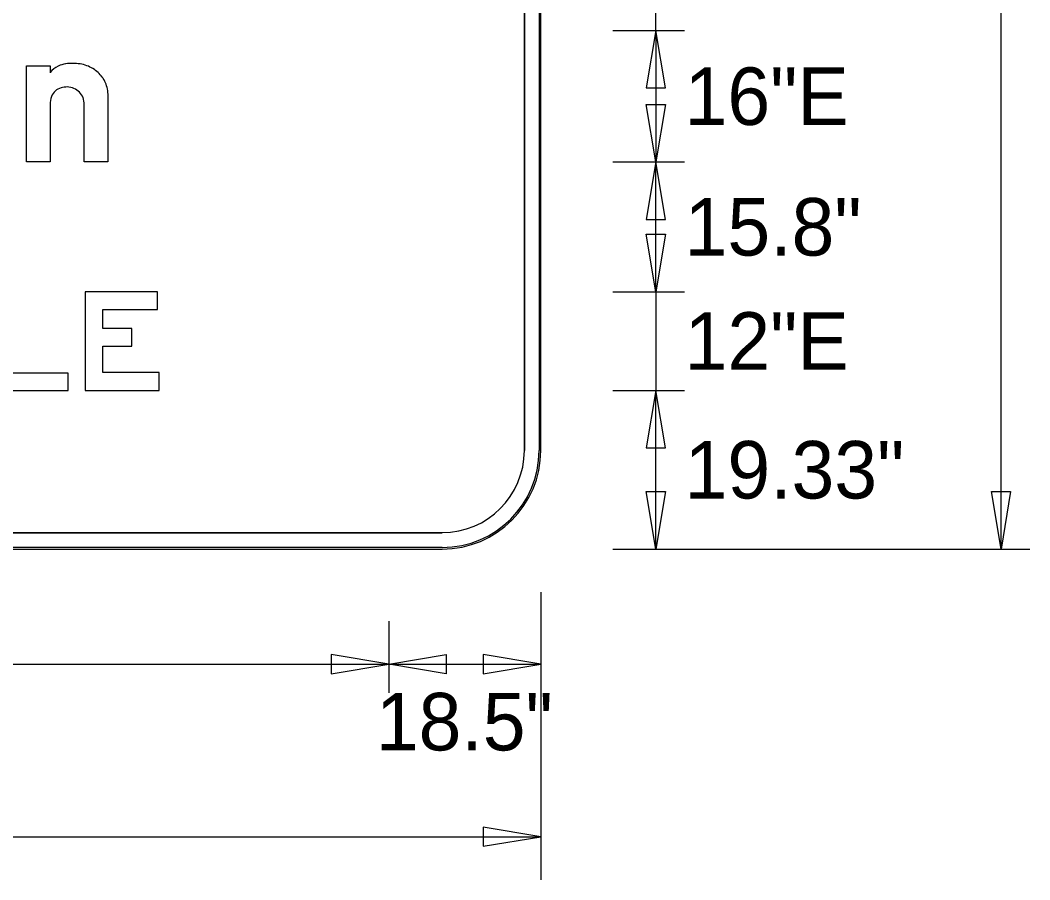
# Model space of a CAD drawing. Extents: x 2149934 to 2150188, y 145113 to 145238.
# Drawn here: x 2150041.74 to 2150051.98, y 145141.03 to 145149.75 of the extents above; entities that cross this region are included whole.
import ezdxf

# ---------------------------------------------------------------- set-up
doc = ezdxf.new("R2010")
doc.units = 0
for name, color, linetype in [('GSBWFILL', 7, 'Continuous'), ('GSCOLORFILL', 7, 'Continuous'), ('GSDIMS', 7, 'Continuous'), ('GSOUTLINE', 7, 'Continuous')]:
    doc.layers.add(name, color=color, linetype=linetype)

msp = doc.modelspace()

# ---------------------------------------------------------------- linework, layer by layer
at = {"layer": 'GSBWFILL'}
for p, q in [((2150046.853, 145156.383), (2150046.853, 145145.383)), ((2150047.02, 145145.383), (2150047.02, 145156.383)), ((2150042.391, 145148.31), (2150042.391, 145148.892)), ((2150046.02, 145144.549), (2150032.522, 145144.549)), ((2150032.522, 145144.383), (2150046.02, 145144.383))]:
    msp.add_line(p, q, dxfattribs=at)
for points in [[(2150042.045, 145148.892), (2150042.045, 145148.31), (2150041.805, 145148.31), (2150041.805, 145149.283), (2150042.045, 145149.283), (2150042.045, 145149.215)], [(2150042.631, 145148.979), (2150042.631, 145148.31), (2150042.391, 145148.31)]]:
    msp.add_lwpolyline(points, dxfattribs=at)
for points in [[(2150042.229, 145145.993), (2150042.229, 145146.168), (2150041.659, 145146.168), (2150041.659, 145146.993), (2150041.479, 145146.993), (2150041.479, 145145.993)], [(2150043.149, 145146.173), (2150042.579, 145146.173), (2150042.579, 145146.442), (2150042.874, 145146.442), (2150042.874, 145146.622), (2150042.579, 145146.622), (2150042.579, 145146.813), (2150043.134, 145146.813), (2150043.134, 145146.993), (2150042.399, 145146.993), (2150042.399, 145145.993), (2150043.149, 145145.993)]]:
    msp.add_lwpolyline(points, close=True, dxfattribs=at)
for radius in [1, 0.833]:
    msp.add_arc((2150046.02, 145145.383), radius, 270, 0, dxfattribs=at)
for centre, major_axis, start_param, end_param in [((2150042.242, 145149.041), (0, 0.267), 0.148374, 0.444839), ((2150042.272, 145148.835), (0, 0.475), 0, 0.148374), ((2150042.272, 145148.848), (0, 0.462), 6.11698, 6.283185), ((2150042.288, 145148.937), (0, 0.372), 5.743536, 6.11991), ((2150042.224, 145149.078), (0, 0.226), 0.444839, 0.915988), ((2150042.317, 145148.986), (0, 0.315), 5.331411, 5.742098), ((2150042.322, 145148.99), (0, 0.309), 4.909454, 5.328907), ((2150042.195, 145148.922), (0, 0.145), 0.274492, 1.206206), ((2150042.218, 145148.847), (0, 0.223), 0, 0.282279), ((2150042.218, 145148.896), (0, 0.174), 5.879574, 6.283185), ((2150042.218, 145148.897), (0, 0.173), 5.093345, 5.87639), ((2150042.249, 145148.979), (0, 0.383), 4.712389, 4.900007), ((2150042.273, 145148.892), (0, 0.228), 1.206869, 1.570796), ((2150042.206, 145148.894), (0, 0.185), 4.705543, 5.088361)]:
    msp.add_ellipse(centre, major_axis=major_axis, ratio=0.999997, start_param=start_param, end_param=end_param, dxfattribs=at)
at = {"layer": 'GSCOLORFILL'}
for p, q in [((2150046.853, 145156.383), (2150046.853, 145145.383)), ((2150047.003, 145156.383), (2150047.003, 145145.383)), ((2150047.02, 145145.383), (2150047.02, 145156.383)), ((2150047.02, 145145.383), (2150047.02, 145156.383)), ((2150047.02, 145145.383), (2150047.02, 145156.383)), ((2150042.391, 145148.31), (2150042.391, 145148.892)), ((2150046.02, 145144.549), (2150032.522, 145144.549)), ((2150046.02, 145144.399), (2150032.52, 145144.399)), ((2150032.52, 145144.383), (2150046.02, 145144.383)), ((2150032.52, 145144.383), (2150046.02, 145144.383)), ((2150032.522, 145144.383), (2150046.02, 145144.383))]:
    msp.add_line(p, q, dxfattribs=at)
for points in [[(2150042.045, 145148.892), (2150042.045, 145148.31), (2150041.805, 145148.31), (2150041.805, 145149.283), (2150042.045, 145149.283), (2150042.045, 145149.215)], [(2150042.631, 145148.979), (2150042.631, 145148.31), (2150042.391, 145148.31)]]:
    msp.add_lwpolyline(points, dxfattribs=at)
for points in [[(2150042.229, 145145.993), (2150042.229, 145146.168), (2150041.659, 145146.168), (2150041.659, 145146.993), (2150041.479, 145146.993), (2150041.479, 145145.993)], [(2150043.149, 145146.173), (2150042.579, 145146.173), (2150042.579, 145146.442), (2150042.874, 145146.442), (2150042.874, 145146.622), (2150042.579, 145146.622), (2150042.579, 145146.813), (2150043.134, 145146.813), (2150043.134, 145146.993), (2150042.399, 145146.993), (2150042.399, 145145.993), (2150043.149, 145145.993)]]:
    msp.add_lwpolyline(points, close=True, dxfattribs=at)
for radius in [1, 1, 0.833, 1, 0.983]:
    msp.add_arc((2150046.02, 145145.383), radius, 270, 0, dxfattribs=at)
for centre, major_axis, start_param, end_param in [((2150042.242, 145149.041), (0, 0.267), 0.148374, 0.444839), ((2150042.272, 145148.835), (0, 0.475), 0, 0.148374), ((2150042.272, 145148.848), (0, 0.462), 6.11698, 6.283185), ((2150042.288, 145148.937), (0, 0.372), 5.743536, 6.11991), ((2150042.224, 145149.078), (0, 0.226), 0.444839, 0.915988), ((2150042.317, 145148.986), (0, 0.315), 5.331411, 5.742098), ((2150042.322, 145148.99), (0, 0.309), 4.909454, 5.328907), ((2150042.195, 145148.922), (0, 0.145), 0.274492, 1.206206), ((2150042.218, 145148.847), (0, 0.223), 0, 0.282279), ((2150042.218, 145148.896), (0, 0.174), 5.879574, 6.283185), ((2150042.218, 145148.897), (0, 0.173), 5.093345, 5.87639), ((2150042.249, 145148.979), (0, 0.383), 4.712389, 4.900007), ((2150042.273, 145148.892), (0, 0.228), 1.206869, 1.570796), ((2150042.206, 145148.894), (0, 0.185), 4.705543, 5.088361)]:
    msp.add_ellipse(centre, major_axis=major_axis, ratio=0.999997, start_param=start_param, end_param=end_param, dxfattribs=at)
at = {"layer": 'GSDIMS'}
for p, q in [((2150048.187, 145149.643), (2150048.187, 145150.643)), ((2150051.687, 145144.383), (2150051.687, 145150.643)), ((2150047.749, 145149.643), (2150048.478, 145149.643)), ((2150047.749, 145149.643), (2150048.478, 145149.643)), ((2150048.187, 145149.643), (2150048.187, 145148.31)), ((2150047.749, 145148.31), (2150048.478, 145148.31)), ((2150047.749, 145148.31), (2150048.478, 145148.31)), ((2150048.187, 145146.993), (2150048.187, 145148.31)), ((2150047.749, 145146.993), (2150048.478, 145146.993)), ((2150047.749, 145146.993), (2150048.478, 145146.993)), ((2150048.187, 145146.993), (2150048.187, 145145.993)), ((2150047.749, 145145.993), (2150048.478, 145145.993)), ((2150047.749, 145145.993), (2150048.478, 145145.993)), ((2150048.187, 145144.383), (2150048.187, 145145.993)), ((2150047.749, 145144.383), (2150048.478, 145144.383)), ((2150047.749, 145144.383), (2150051.249, 145144.383)), ((2150051.249, 145144.383), (2150051.978, 145144.383)), ((2150047.02, 145143.945), (2150047.02, 145141.028)), ((2150045.478, 145143.653), (2150045.478, 145142.924)), ((2150045.478, 145143.653), (2150045.478, 145142.924)), ((2150047.02, 145143.653), (2150047.02, 145142.924)), ((2150033.061, 145143.216), (2150045.478, 145143.216)), ((2150045.478, 145143.216), (2150047.02, 145143.216)), ((2150047.02, 145141.903), (2150047.02, 145141.174)), ((2150031.52, 145141.466), (2150047.02, 145141.466))]:
    msp.add_line(p, q, dxfattribs=at)
for points in [[(2150048.187, 145149.643), (2150048.089, 145149.06), (2150048.284, 145149.06)], [(2150048.187, 145148.31), (2150048.089, 145148.893), (2150048.284, 145148.893)], [(2150048.187, 145148.31), (2150048.089, 145147.727), (2150048.284, 145147.727)], [(2150048.187, 145146.993), (2150048.089, 145147.577), (2150048.284, 145147.577)], [(2150048.187, 145145.993), (2150048.089, 145145.41), (2150048.284, 145145.41)], [(2150048.187, 145144.383), (2150048.089, 145144.966), (2150048.284, 145144.966)], [(2150051.687, 145144.383), (2150051.589, 145144.966), (2150051.784, 145144.966)], [(2150045.478, 145143.216), (2150044.895, 145143.313), (2150044.895, 145143.119)], [(2150045.478, 145143.216), (2150046.062, 145143.313), (2150046.062, 145143.119)], [(2150047.02, 145143.216), (2150046.437, 145143.313), (2150046.437, 145143.119)], [(2150047.02, 145141.466), (2150046.437, 145141.563), (2150046.437, 145141.369)]]:
    msp.add_lwpolyline(points, close=True, dxfattribs=at)
at = {"layer": 'GSOUTLINE'}
for p, q in [((2150046.853, 145145.383), (2150046.853, 145156.383)), ((2150047.02, 145145.383), (2150047.02, 145156.383)), ((2150042.391, 145148.31), (2150042.391, 145148.892)), ((2150032.52, 145144.549), (2150046.02, 145144.549)), ((2150032.52, 145144.383), (2150046.02, 145144.383))]:
    msp.add_line(p, q, dxfattribs=at)
for points in [[(2150042.045, 145148.892), (2150042.045, 145148.31), (2150041.805, 145148.31), (2150041.805, 145149.283), (2150042.045, 145149.283), (2150042.045, 145149.215)], [(2150042.631, 145148.979), (2150042.631, 145148.31), (2150042.391, 145148.31)]]:
    msp.add_lwpolyline(points, dxfattribs=at)
for points in [[(2150042.229, 145145.993), (2150042.229, 145146.168), (2150041.659, 145146.168), (2150041.659, 145146.993), (2150041.479, 145146.993), (2150041.479, 145145.993)], [(2150043.149, 145146.173), (2150042.579, 145146.173), (2150042.579, 145146.442), (2150042.874, 145146.442), (2150042.874, 145146.622), (2150042.579, 145146.622), (2150042.579, 145146.813), (2150043.134, 145146.813), (2150043.134, 145146.993), (2150042.399, 145146.993), (2150042.399, 145145.993), (2150043.149, 145145.993)]]:
    msp.add_lwpolyline(points, close=True, dxfattribs=at)
for radius in [1, 0.833]:
    msp.add_arc((2150046.02, 145145.383), radius, 270, 0, dxfattribs=at)
for centre, major_axis, start_param, end_param in [((2150042.242, 145149.041), (0, 0.267), 0.148374, 0.444839), ((2150042.272, 145148.835), (0, 0.475), 0, 0.148374), ((2150042.272, 145148.848), (0, 0.462), 6.11698, 6.283185), ((2150042.288, 145148.937), (0, 0.372), 5.743536, 6.11991), ((2150042.224, 145149.078), (0, 0.226), 0.444839, 0.915988), ((2150042.317, 145148.986), (0, 0.315), 5.331411, 5.742098), ((2150042.322, 145148.99), (0, 0.309), 4.909454, 5.328907), ((2150042.195, 145148.922), (0, 0.145), 0.274492, 1.206206), ((2150042.218, 145148.847), (0, 0.223), 0, 0.282279), ((2150042.218, 145148.896), (0, 0.174), 5.879574, 6.283185), ((2150042.218, 145148.897), (0, 0.173), 5.093345, 5.87639), ((2150042.249, 145148.979), (0, 0.383), 4.712389, 4.900007), ((2150042.273, 145148.892), (0, 0.228), 1.206869, 1.570796), ((2150042.206, 145148.894), (0, 0.185), 4.705543, 5.088361)]:
    msp.add_ellipse(centre, major_axis=major_axis, ratio=0.999997, start_param=start_param, end_param=end_param, dxfattribs=at)

# ---------------------------------------------------------------- texts
at = {"layer": 'GSDIMS'}
for s, p in [('16"E', (2150048.478, 145148.685)), ('15.8"', (2150048.478, 145147.36)), ('12"E', (2150048.478, 145146.202)), ('19.33"', (2150048.478, 145144.896)), ('18.5"', (2150045.347, 145142.341))]:
    msp.add_text(s, height=0.5833, dxfattribs=at).set_placement(p)

doc.saveas('drawing.dxf')
